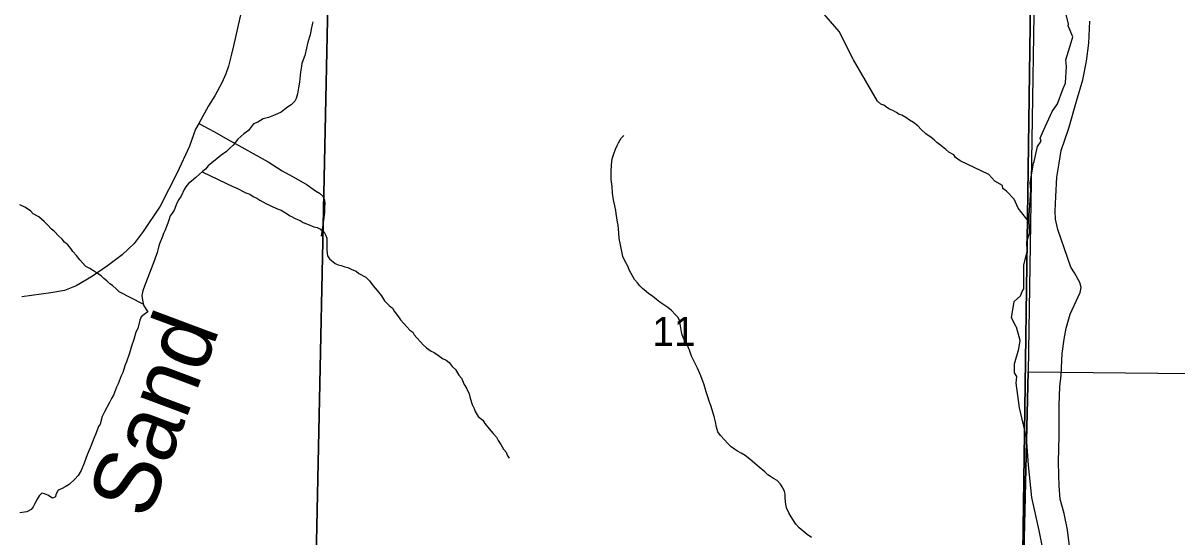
# Model space of a CAD drawing. Extents: x 0 to 34, y 0 to 22.
# Drawn here: x 5.636 to 7.298, y 18.569 to 19.309 of the extents above; entities that cross this region are included whole.
import ezdxf

# ---------------------------------------------------------------- set-up
doc = ezdxf.new("R2010")
doc.units = 0
for name, color, linetype in [('GM_X_Corporation', 7, 'Continuous'), ('GM_X_County_Road', 7, 'Continuous'), ('GM_X_Minor_River', 7, 'Continuous'), ('GM_X_Minor_River_Text', 7, 'Continuous'), ('GM_X_Section_Text', 7, 'Continuous'), ('GM_X_Township_Road', 7, 'Continuous')]:
    doc.layers.add(name, color=color, linetype=linetype)

msp = doc.modelspace()

# ---------------------------------------------------------------- linework, layer by layer
at = {"layer": 'GM_X_Corporation'}
msp.add_lwpolyline([(4.9914, 16.3477), (5.6931, 16.3352), (5.9938, 16.3204), (6.9309, 16.303), (7.0302, 16.2995), (7.0306, 16.367), (7.0337, 16.3927), (7.0334, 16.423), (7.0339, 16.4517), (7.0342, 16.5147), (7.0361, 16.5712), (7.0442, 17.0463), (7.0729, 18.3402), (7.0876, 19.4092), (7.1008, 19.81), (7.1249, 20.7061), (7.1302, 20.9), (2.2795, 20.9)], dxfattribs=at)
for points in [[(8.9, 16.2485), (8.9, 20.9), (7.1302, 20.9), (7.1249, 20.7061), (7.1008, 19.81), (7.0876, 19.4092), (7.0729, 18.3402), (7.0442, 17.0463), (7.0361, 16.5712), (7.0342, 16.5147), (7.0339, 16.4517), (7.0334, 16.423), (7.0337, 16.3927), (7.0306, 16.367), (7.0302, 16.2995), (7.0491, 16.2993), (8.0233, 16.275), (8.785, 16.2515)], [(5.0447, 19.4257), (6.0762, 19.405), (6.0547, 18.3798), (5.0167, 18.3983)], [(6.0762, 19.405), (7.0925, 19.3811), (7.0882, 19.1112), (7.0832, 18.8066), (7.0725, 18.3472), (6.0547, 18.3798)], [(7.0832, 18.8066), (7.5969, 18.8015), (8.1004, 18.7963), (8.0825, 18.3198), (7.0725, 18.3472)]]:
    msp.add_lwpolyline(points, close=True, dxfattribs=at)
at = {"layer": 'GM_X_County_Road'}
msp.add_lwpolyline([(5.9539, 19.3417), (5.9389, 19.2759), (5.9358, 19.2642), (5.9319, 19.2467), (5.9279, 19.2356), (5.9222, 19.2227), (5.912, 19.2041), (5.9029, 19.1896), (5.8889, 19.1642), (5.8843, 19.156), (5.8755, 19.1316), (5.8576, 19.0931), (5.8334, 19.0453), (5.8087, 19.0086), (5.796, 18.9916), (5.7785, 18.9752), (5.7572, 18.9594), (5.7345, 18.9437), (5.7121, 18.9304), (5.6953, 18.924), (5.6759, 18.9204), (5.6339, 18.9145)], dxfattribs=at)
at = {"layer": 'GM_X_Minor_River'}
for points in [[(7.0266, 19.0906), (6.9856, 19.1107), (6.9788, 19.1152), (6.9761, 19.119), (6.9693, 19.1231), (6.9647, 19.1269), (6.9575, 19.1326), (6.9518, 19.1368), (6.948, 19.1409), (6.9434, 19.1439), (6.9358, 19.1492), (6.929, 19.1557), (6.9244, 19.161), (6.918, 19.1655), (6.9123, 19.1689), (6.907, 19.1731), (6.9013, 19.1765), (6.8975, 19.1772), (6.8937, 19.1799), (6.8884, 19.1829), (6.8834, 19.1848), (6.8796, 19.1871), (6.8755, 19.1905), (6.8713, 19.1923), (6.8664, 19.1965), (6.8317, 19.256), (6.8111, 19.2965), (6.7522, 19.3655)], [(7.1384, 19.2464), (7.1377, 19.2559), (7.1453, 19.2809), (7.1476, 19.2892), (7.1409, 19.3048), (7.1412, 19.3071), (7.1338, 19.3385)], [(6.0532, 19.3106), (6.0521, 19.3068), (6.0506, 19.3003), (6.0491, 19.292), (6.0461, 19.2814), (6.0442, 19.2726), (6.0416, 19.2624), (6.039, 19.2559), (6.0371, 19.2506), (6.0367, 19.2468), (6.0352, 19.2381), (6.0338, 19.2237), (6.0326, 19.2157), (6.0312, 19.207), (6.0293, 19.2002), (6.0274, 19.1964), (6.0217, 19.191), (6.0168, 19.188), (6.0123, 19.1842), (6.0074, 19.1808), (6.0024, 19.1781), (5.9964, 19.1758), (5.9892, 19.1728), (5.9816, 19.1709), (5.9741, 19.1663), (5.9676, 19.1636), (5.9605, 19.1541), (5.954, 19.1496), (5.945, 19.1416), (5.9382, 19.1329), (5.934, 19.1291), (5.9287, 19.1241), (5.9208, 19.118), (5.9026, 19.1032), (5.8985, 19.0986), (5.8943, 19.0952), (5.8898, 19.0914), (5.8845, 19.0865), (5.8784, 19.0812), (5.8739, 19.0777), (5.8701, 19.0732), (5.8679, 19.069), (5.8637, 19.0595), (5.86, 19.055), (5.8573, 19.0496), (5.8532, 19.0394), (5.8505, 19.0352), (5.8475, 19.0314), (5.8464, 19.0265), (5.8441, 19.0208), (5.84, 19.0098), (5.8381, 19.006), (5.8366, 19.0014), (5.8325, 18.9908), (5.831, 18.9863), (5.8291, 18.9783), (5.825, 18.9673), (5.8205, 18.9548), (5.8156, 18.9426)], [(7.1094, 18.5285), (7.099, 18.5781), (7.0885, 18.6259), (7.0837, 18.6721), (7.0808, 18.7123), (7.0707, 18.7551), (7.0658, 18.7904), (7.067, 18.8002), (7.0636, 18.8052), (7.0636, 18.8181), (7.0701, 18.84), (7.0717, 18.8517), (7.0664, 18.8711), (7.0657, 18.8722), (7.0593, 18.8851), (7.0612, 18.8961), (7.0631, 18.9079), (7.0722, 18.9162), (7.0749, 18.9226), (7.0771, 18.926), (7.0772, 18.9605), (7.0818, 18.9798), (7.0815, 18.9942), (7.0853, 19.0063), (7.0846, 19.0317), (7.0873, 19.0688), (7.0862, 19.0787), (7.0908, 19.1071), (7.092, 19.1097), (7.0966, 19.1313), (7.1019, 19.1389), (7.1004, 19.1431), (7.1053, 19.1544), (7.1179, 19.1817), (7.1254, 19.1926), (7.1338, 19.2146), (7.1372, 19.2225), (7.1384, 19.2464)], [(6.5425, 18.9156), (6.5371, 18.919), (6.533, 18.9224), (6.528, 18.9266), (6.5242, 18.9303), (6.5208, 18.9349), (6.5166, 18.9398), (6.5139, 18.944), (6.5094, 18.9527), (6.5067, 18.9588), (6.5025, 18.9663), (6.4998, 18.9728), (6.4979, 18.98), (6.4964, 18.9898), (6.4945, 18.9989), (6.4937, 19.0069), (6.4929, 19.0179), (6.4921, 19.0224), (6.4902, 19.0349), (6.4894, 19.0391), (6.4879, 19.0459), (6.4863, 19.0543), (6.4848, 19.0638), (6.484, 19.0736), (6.4828, 19.0835), (6.4828, 19.0945), (6.4831, 19.1047), (6.4835, 19.1093), (6.4843, 19.1134), (6.4865, 19.1207), (6.4891, 19.1275), (6.4914, 19.1324), (6.4933, 19.1362), (6.4971, 19.1431), (6.5008, 19.1469)], [(5.8939, 19.0949), (5.9391, 19.0729), (5.9429, 19.0718), (5.9467, 19.0699), (5.952, 19.0669), (5.9566, 19.0646), (5.9622, 19.0624), (5.9672, 19.0593), (5.9725, 19.0567), (5.9767, 19.0537), (5.9812, 19.0514), (5.9862, 19.0484), (5.99, 19.0472), (5.9938, 19.045), (6.001, 19.042), (6.0074, 19.0397), (6.0139, 19.0355), (6.0207, 19.0314), (6.0287, 19.0268), (6.0351, 19.0246), (6.0393, 19.0219), (6.0454, 19.0193), (6.0548, 19.0155), (6.0594, 19.0144), (6.0643, 19.0121), (6.0693, 19.008), (6.0719, 19.003), (6.0731, 18.9992), (6.0735, 18.9935), (6.0735, 18.9822), (6.0739, 18.9772), (6.0743, 18.9735), (6.077, 18.9693), (6.0853, 18.9625), (6.0895, 18.9606), (6.0937, 18.9598), (6.099, 18.958), (6.1035, 18.9568), (6.1092, 18.9542), (6.1157, 18.9515), (6.1195, 18.9485), (6.1293, 18.9428), (6.1347, 18.9375), (6.14, 18.9307), (6.1457, 18.9239), (6.1522, 18.916), (6.1563, 18.9088), (6.1632, 18.902), (6.1681, 18.8982), (6.1704, 18.894), (6.1765, 18.8861), (6.1795, 18.8815), (6.1849, 18.8758), (6.1887, 18.8713), (6.1928, 18.8667), (6.197, 18.8637), (6.1993, 18.8599), (6.2027, 18.8558), (6.2084, 18.8497), (6.2119, 18.8455), (6.2168, 18.8414), (6.2236, 18.8365), (6.2278, 18.8346), (6.2339, 18.83), (6.24, 18.8259), (6.2453, 18.8236), (6.2495, 18.8202), (6.254, 18.8142), (6.2586, 18.81), (6.2635, 18.8017), (6.267, 18.7975), (6.2711, 18.7884), (6.2742, 18.7831), (6.2784, 18.7752), (6.2799, 18.7687), (6.2826, 18.7596), (6.2853, 18.7539), (6.2868, 18.7498), (6.291, 18.7422), (6.2978, 18.7369), (6.3009, 18.7323), (6.307, 18.7248), (6.3127, 18.718), (6.3176, 18.7127), (6.3199, 18.7077), (6.3237, 18.7021), (6.3279, 18.6952), (6.3317, 18.6911), (6.3332, 18.6865), (6.3359, 18.6824)], [(7.0848, 19.0221), (7.0687, 19.0424), (7.0631, 19.0553), (7.0521, 19.0667), (7.0469, 19.0708), (7.0465, 19.075), (7.0352, 19.0811), (7.0266, 19.0906)], [(5.809, 18.9039), (5.7743, 18.9221), (5.7702, 18.9258), (5.7648, 18.9311), (5.761, 18.9334), (5.7565, 18.9376), (5.7523, 18.9413), (5.7485, 18.9451), (5.7428, 18.9482), (5.7371, 18.9523), (5.7322, 18.9553), (5.7261, 18.9584), (5.7212, 18.9637), (5.7177, 18.9678), (5.7128, 18.9743), (5.7075, 18.9799), (5.7044, 18.9845), (5.7003, 18.9894), (5.6957, 18.9932), (5.6919, 18.9977), (5.6869, 19.0023), (5.6812, 19.0087), (5.6767, 19.0121), (5.671, 19.0182), (5.6664, 19.0231), (5.6584, 19.0299), (5.6505, 19.0344), (5.6463, 19.0386), (5.6383, 19.0439), (5.6311, 19.0473)], [(5.8156, 18.9426), (5.8111, 18.9316), (5.8084, 18.9233), (5.807, 18.9164), (5.8077, 18.91), (5.8093, 18.9028), (5.8131, 18.8967), (5.8154, 18.8929), (5.8101, 18.8891), (5.8059, 18.8861), (5.804, 18.8812), (5.801, 18.869), (5.7984, 18.8637), (5.7954, 18.8531), (5.792, 18.8436), (5.789, 18.8337), (5.7849, 18.8212), (5.783, 18.817), (5.7796, 18.8056), (5.777, 18.8011), (5.7729, 18.7893), (5.7702, 18.7848), (5.7661, 18.773), (5.7631, 18.7685), (5.7604, 18.7624), (5.7533, 18.7491), (5.7499, 18.7423), (5.7469, 18.7316), (5.7446, 18.7278), (5.7412, 18.7191), (5.7367, 18.7081), (5.7326, 18.6975), (5.7281, 18.6872), (5.7239, 18.6751), (5.7194, 18.6645), (5.7153, 18.6576), (5.7104, 18.652), (5.7024, 18.6447), (5.6964, 18.6413), (5.6919, 18.6386), (5.6866, 18.6364), (5.6832, 18.6303), (5.6824, 18.6265), (5.6783, 18.6246), (5.6714, 18.6291), (5.6665, 18.631), (5.6627, 18.6321), (5.6589, 18.628), (5.6563, 18.6234), (5.6529, 18.617), (5.6503, 18.6124), (5.6476, 18.6086), (5.6412, 18.6052), (5.631, 18.6036)], [(6.7713, 18.568), (6.7652, 18.5725), (6.7591, 18.5774), (6.7534, 18.582), (6.7488, 18.5873), (6.742, 18.5979), (6.7386, 18.6036), (6.7355, 18.6108), (6.734, 18.6191), (6.7336, 18.6263), (6.7332, 18.6305), (6.7324, 18.6346), (6.7301, 18.6396), (6.7267, 18.6449), (6.7217, 18.6502), (6.7164, 18.6532), (6.7123, 18.6562), (6.7085, 18.6585), (6.7039, 18.6626), (6.6959, 18.6694), (6.6895, 18.6747), (6.6826, 18.6812), (6.6758, 18.6861), (6.6701, 18.6895), (6.6648, 18.6925), (6.6606, 18.6955), (6.6557, 18.6986), (6.6515, 18.7031), (6.6401, 18.7152), (6.6363, 18.7201), (6.6344, 18.7269), (6.6328, 18.7349), (6.6309, 18.7425), (6.629, 18.7485), (6.6267, 18.7569), (6.624, 18.7645), (6.6221, 18.7705), (6.6198, 18.7777), (6.6167, 18.788), (6.6121, 18.8008), (6.6072, 18.8118), (6.5984, 18.8292), (6.5957, 18.838), (6.5927, 18.8444), (6.5896, 18.8505), (6.587, 18.8554), (6.5851, 18.8599), (6.5839, 18.8645), (6.5827, 18.8728), (6.5812, 18.8804), (6.5793, 18.885), (6.5751, 18.8891), (6.5698, 18.8948), (6.5645, 18.8993), (6.5603, 18.902), (6.5531, 18.9069), (6.5482, 18.9107), (6.5425, 18.9156)]]:
    msp.add_lwpolyline(points, dxfattribs=at)
at = {"layer": 'GM_X_Township_Road'}
for points in [[(7.1427, 18.5558), (7.1398, 18.5791), (7.1353, 18.6029), (7.1296, 18.6235), (7.1278, 18.6426), (7.1273, 18.6578), (7.1269, 18.6772), (7.128, 18.7146), (7.128, 18.7588), (7.1289, 18.7853), (7.1307, 18.8021), (7.1321, 18.8329), (7.1353, 18.8538), (7.1379, 18.8697), (7.1439, 18.8899), (7.1582, 18.9209), (7.1595, 18.9283), (7.1577, 18.9354), (7.15, 18.9494), (7.145, 18.9576), (7.1398, 18.9712), (7.1262, 19.0117), (7.1226, 19.0267), (7.1221, 19.0382), (7.1233, 19.0593), (7.1248, 19.087), (7.1278, 19.1071), (7.1307, 19.1253), (7.1418, 19.1574), (7.1528, 19.1963), (7.162, 19.2271), (7.1674, 19.2542), (7.1706, 19.2798), (7.172, 19.3115)], [(5.8889, 19.1642), (5.9106, 19.1527), (5.9317, 19.1409), (5.9507, 19.1302), (5.9716, 19.1185), (5.9888, 19.1092), (6.0088, 19.0963), (6.0289, 19.0849), (6.0448, 19.0761), (6.0572, 19.0675), (6.0629, 19.0638), (6.0675, 19.0598), (6.0697, 19.0541), (6.0702, 19.0489), (6.0699, 19.0439), (6.0699, 19.036), (6.0686, 19.0253), (6.0652, 19.002)]]:
    msp.add_lwpolyline(points, dxfattribs=at)

# ---------------------------------------------------------------- texts
at = {"layer": 'GM_X_Minor_River_Text'}
msp.add_text('Sand', height=0.09462, rotation=69.4811, dxfattribs=at).set_placement((5.8158, 18.5916))
at = {"layer": 'GM_X_Section_Text'}
msp.add_text('11', height=0.04186, rotation=0, dxfattribs=at).set_placement((6.542, 18.844))

doc.saveas('drawing.dxf')
